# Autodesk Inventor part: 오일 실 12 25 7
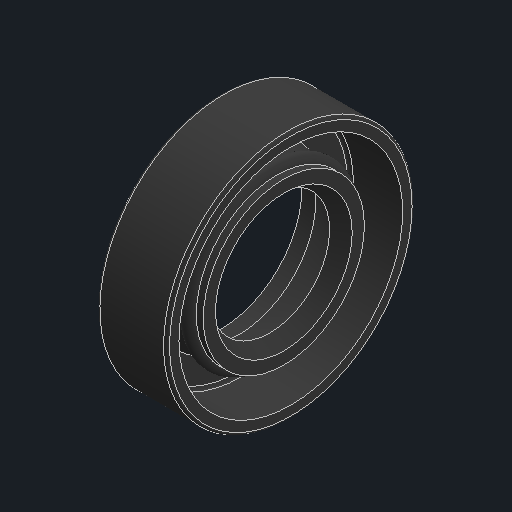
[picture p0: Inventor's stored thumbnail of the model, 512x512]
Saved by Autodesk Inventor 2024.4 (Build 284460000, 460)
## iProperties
Created: 2026-03
Part Number: 오일 실 12 25 7
Material: 고무
Description: 오일-실
Document SubType Name: Modeling
Designer: user
Density: 0.93 g/cm^3
Appearance: 기본값
Author: jhkim
Sending System: Autodesk Inventor 2026
Preprocessor: ST-DEVELOPER v20.1
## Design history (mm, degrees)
feature "Solid1"
node "솔리드1"
